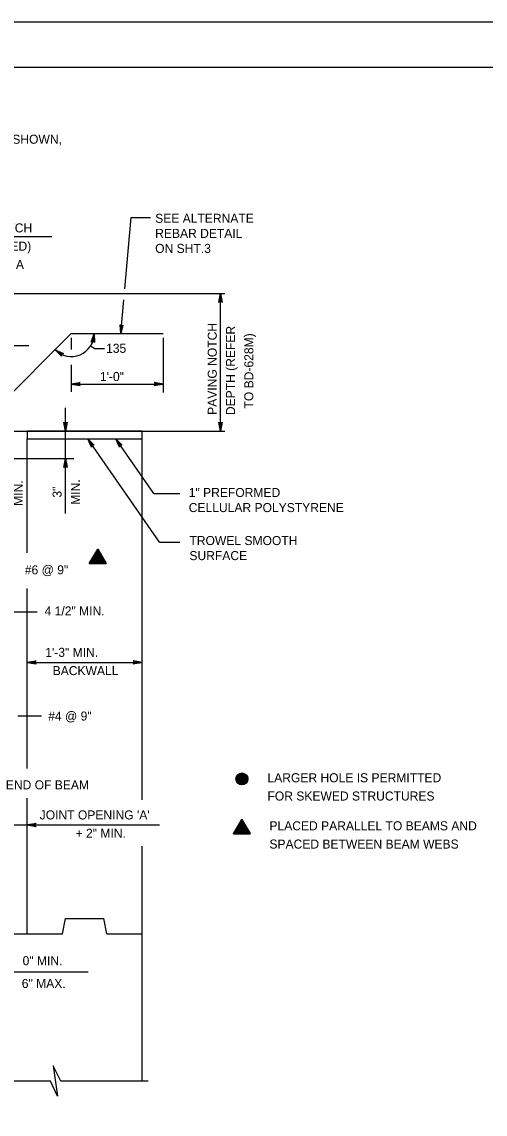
# Model space of a CAD drawing. Extents: x 640009 to 641706, y 298547 to 299735.
# Drawn here: x 641121.1 to 641275, y 299372.4 to 299735.2 of the extents above; entities that cross this region are included whole.
import ezdxf

# ---------------------------------------------------------------- set-up
doc = ezdxf.new("R2010")
doc.units = 0
doc.layers.add('1', color=7, linetype='Continuous')
doc.layers.add('PLT-BNDY', color=7, linetype='Continuous')

msp = doc.modelspace()

# ---------------------------------------------------------------- linework, layer by layer
at = {"layer": '1'}
for p, q in [((640890.47, 299720.17), (641676.47, 299720.17)), ((640890.47, 299720.17), (641676.47, 299720.17)), ((641155.32, 299646.47), (641157.48, 299670.24)), ((641157.48, 299670.24), (641163.84, 299670.24)), ((641092.08, 299663.84), (641131.12, 299663.84)), ((641088.34, 299645), (641188.58, 299645)), ((641153.97, 299631.67), (641154.99, 299642.85)), ((641187.12, 299599.28), (641187.12, 299645)), ((641074.63, 299568.75), (641137.55, 299631.67)), ((641137.55, 299631.67), (641168.03, 299631.67)), ((641137.55, 299630.26), (641137.55, 299626.36)), ((641168.03, 299630.26), (641168.03, 299612.06)), ((641099.21, 299627.64), (641123.44, 299627.64)), ((641143.97, 299627.56), (641145.38, 299626.66)), ((641145.38, 299626.66), (641148.53, 299626.66)), ((641137.55, 299621.31), (641137.55, 299612.34)), ((641137.55, 299614.87), (641168.03, 299614.87)), ((641135.6, 299590.2), (641135.6, 299607.02)), ((641110.25, 299599.28), (641188.58, 299599.28)), ((641122.94, 299599.28), (641161.04, 299599.28)), ((641122.94, 299596.74), (641161.04, 299596.74)), ((641122.94, 299558.81), (641122.94, 299596.74)), ((641166.84, 299562.38), (641143.02, 299596.74)), ((641164.96, 299578.49), (641152.31, 299596.74)), ((641161.04, 299476.82), (641161.04, 299597.38)), ((641111.67, 299590.2), (641138.43, 299590.2)), ((641135.6, 299571.86), (641135.6, 299590.2)), ((641164.96, 299578.49), (641173.62, 299578.49)), ((641166.84, 299562.38), (641173.58, 299562.38)), ((641146.32, 299556.87), (641146.32, 299556.87)), ((641122.94, 299487.19), (641122.94, 299547.03)), ((641089.62, 299539.2), (641126.24, 299539.2)), ((641122.94, 299522.45), (641161.04, 299522.45)), ((641119.82, 299504.67), (641127.64, 299504.67)), ((641122.94, 299432.28), (641122.94, 299477.38)), ((641046.74, 299468.48), (641166.85, 299468.48)), ((641194.23, 299467.14), (641194.23, 299467.14)), ((641161.04, 299432.28), (641161.04, 299461.41)), ((641134.63, 299432.28), (641135.65, 299437.38)), ((641135.65, 299437.38), (641148.34, 299437.38)), ((641149.36, 299432.28), (641148.34, 299437.38)), ((641048.65, 299432.28), (641122.94, 299432.28)), ((641122.94, 299432.28), (641134.63, 299432.28)), ((641149.36, 299432.28), (641161.04, 299432.28)), ((641161.04, 299383.32), (641161.04, 299432.28)), ((641116.39, 299419.71), (641143.2, 299419.71)), ((641130.59, 299383.32), (641081.97, 299383.32)), ((641163.08, 299383.32), (641134.11, 299383.32))]:
    msp.add_line(p, q, dxfattribs=at)
for points in [[(641187.12, 299645), (641187.68, 299642.02), (641187.52, 299642.25), (641187.32, 299642.37), (641187.12, 299642.4), (641186.92, 299642.37), (641186.72, 299642.25), (641186.56, 299642.02), (641187.12, 299645), (641186.72, 299642.25), (641186.92, 299642.37), (641187.12, 299645), (641187.12, 299642.4), (641187.32, 299642.37), (641187.12, 299645), (641187.52, 299642.25)], [(641154.56, 299634.35), (641154.35, 299634.27), (641153.97, 299631.67), (641154.56, 299634.35), (641154.69, 299634.48), (641153.97, 299631.67), (641154.08, 299634.29), (641153.89, 299634.4), (641153.97, 299631.67), (641153.78, 299634.56), (641153.89, 299634.4)], [(641145.17, 299631.67), (641145.21, 299628.63), (641145.15, 299628.76), (641145.09, 299628.89), (641145, 299628.96), (641144.91, 299629.04), (641144.82, 299629.07), (641144.72, 299629.11), (641144.62, 299629.11), (641144.52, 299629.11), (641144.41, 299629.07), (641144.3, 299629.03), (641144.2, 299628.93), (641144.11, 299628.83), (641145.17, 299631.67), (641144.2, 299628.93), (641144.3, 299629.03), (641145.17, 299631.67), (641144.41, 299629.07), (641144.52, 299629.11), (641145.17, 299631.67), (641144.62, 299629.11), (641144.72, 299629.11), (641145.17, 299631.67), (641144.82, 299629.07), (641144.91, 299629.04), (641145.17, 299631.67), (641145, 299628.96), (641145.09, 299628.89), (641145.17, 299631.67), (641145.15, 299628.76)], [(641132.17, 299626.28), (641134.94, 299625.05), (641134.8, 299625.05), (641134.66, 299625.05), (641134.55, 299625), (641134.45, 299624.95), (641134.38, 299624.88), (641134.31, 299624.8), (641134.26, 299624.71), (641134.22, 299624.62), (641134.21, 299624.5), (641134.2, 299624.39), (641134.25, 299624.26), (641134.3, 299624.13), (641132.17, 299626.28), (641134.25, 299624.26), (641134.2, 299624.39), (641132.17, 299626.28), (641134.21, 299624.5), (641134.22, 299624.62), (641132.17, 299626.28), (641134.26, 299624.71), (641134.31, 299624.8), (641132.17, 299626.28), (641134.38, 299624.88), (641134.45, 299624.95), (641132.17, 299626.28), (641134.55, 299625), (641134.66, 299625.05), (641132.17, 299626.28), (641134.8, 299625.05)], [(641137.55, 299614.87), (641140.54, 299615.43), (641140.42, 299615.35), (641140.31, 299615.27), (641140.25, 299615.17), (641140.19, 299615.07), (641140.17, 299614.97), (641140.15, 299614.87), (641140.17, 299614.77), (641140.19, 299614.67), (641140.25, 299614.57), (641140.31, 299614.47), (641140.42, 299614.39), (641140.54, 299614.32), (641137.55, 299614.87), (641140.42, 299614.39), (641140.31, 299614.47), (641137.55, 299614.87), (641140.25, 299614.57), (641140.19, 299614.67), (641137.55, 299614.87), (641140.17, 299614.77), (641140.15, 299614.87), (641137.55, 299614.87), (641140.17, 299614.97), (641140.19, 299615.07), (641137.55, 299614.87), (641140.25, 299615.17), (641140.31, 299615.27), (641137.55, 299614.87), (641140.42, 299615.35)], [(641168.03, 299614.87), (641165.05, 299614.32), (641165.17, 299614.39), (641165.28, 299614.47), (641165.34, 299614.57), (641165.4, 299614.67), (641165.42, 299614.77), (641165.43, 299614.87), (641165.42, 299614.97), (641165.4, 299615.07), (641165.34, 299615.17), (641165.28, 299615.27), (641165.17, 299615.35), (641165.05, 299615.43), (641168.03, 299614.87), (641165.17, 299615.35), (641165.28, 299615.27), (641168.03, 299614.87), (641165.34, 299615.17), (641165.4, 299615.07), (641168.03, 299614.87), (641165.42, 299614.97), (641165.43, 299614.87), (641168.03, 299614.87), (641165.42, 299614.77), (641165.4, 299614.67), (641168.03, 299614.87), (641165.34, 299614.57), (641165.28, 299614.47), (641168.03, 299614.87), (641165.17, 299614.39)], [(641135.6, 299599.28), (641135.04, 299602.26), (641135.12, 299602.15), (641135.2, 299602.03), (641135.3, 299601.97), (641135.4, 299601.91), (641135.5, 299601.9), (641135.6, 299601.88), (641135.7, 299601.9), (641135.8, 299601.91), (641135.9, 299601.97), (641136, 299602.03), (641136.08, 299602.15), (641136.16, 299602.26), (641135.6, 299599.28), (641136.08, 299602.15), (641136, 299602.03), (641135.6, 299599.28), (641135.9, 299601.97), (641135.8, 299601.91), (641135.6, 299599.28), (641135.7, 299601.9), (641135.6, 299601.88), (641135.6, 299599.28), (641135.5, 299601.9), (641135.4, 299601.91), (641135.6, 299599.28), (641135.3, 299601.97), (641135.2, 299602.03), (641135.6, 299599.28), (641135.12, 299602.15)], [(641187.12, 299599.28), (641186.56, 299602.26), (641186.72, 299602.03), (641186.92, 299601.91), (641187.12, 299601.88), (641187.32, 299601.91), (641187.52, 299602.03), (641187.68, 299602.26), (641187.12, 299599.28), (641187.52, 299602.03), (641187.32, 299601.91), (641187.12, 299599.28), (641187.12, 299601.88), (641186.92, 299601.91), (641187.12, 299599.28), (641186.72, 299602.03)], [(641143.02, 299596.74), (641145.18, 299594.61), (641145.05, 299594.66), (641144.92, 299594.71), (641144.8, 299594.7), (641144.69, 299594.69), (641144.6, 299594.65), (641144.5, 299594.6), (641144.43, 299594.53), (641144.36, 299594.46), (641144.31, 299594.36), (641144.26, 299594.25), (641144.26, 299594.11), (641144.26, 299593.97), (641143.02, 299596.74), (641144.26, 299594.11), (641144.26, 299594.25), (641143.02, 299596.74), (641144.31, 299594.36), (641144.36, 299594.46), (641143.02, 299596.74), (641144.43, 299594.53), (641144.5, 299594.6), (641143.02, 299596.74), (641144.6, 299594.65), (641144.69, 299594.69), (641143.02, 299596.74), (641144.8, 299594.7), (641144.92, 299594.71), (641143.02, 299596.74), (641145.05, 299594.66)], [(641152.31, 299596.74), (641154.46, 299594.61), (641154.33, 299594.66), (641154.2, 299594.71), (641154.09, 299594.7), (641153.97, 299594.69), (641153.88, 299594.65), (641153.79, 299594.6), (641153.71, 299594.53), (641153.64, 299594.46), (641153.59, 299594.36), (641153.55, 299594.25), (641153.55, 299594.11), (641153.55, 299593.97), (641152.31, 299596.74), (641153.55, 299594.11), (641153.55, 299594.25), (641152.31, 299596.74), (641153.59, 299594.36), (641153.64, 299594.46), (641152.31, 299596.74), (641153.71, 299594.53), (641153.79, 299594.6), (641152.31, 299596.74), (641153.88, 299594.65), (641153.97, 299594.69), (641152.31, 299596.74), (641154.09, 299594.7), (641154.2, 299594.71), (641152.31, 299596.74), (641154.33, 299594.66)], [(641135.6, 299590.2), (641136.16, 299587.22), (641136.08, 299587.33), (641136, 299587.45), (641135.9, 299587.51), (641135.8, 299587.56), (641135.7, 299587.58), (641135.6, 299587.6), (641135.5, 299587.58), (641135.4, 299587.56), (641135.3, 299587.51), (641135.2, 299587.45), (641135.12, 299587.33), (641135.04, 299587.22), (641135.6, 299590.2), (641135.12, 299587.33), (641135.2, 299587.45), (641135.6, 299590.2), (641135.3, 299587.51), (641135.4, 299587.56), (641135.6, 299590.2), (641135.5, 299587.58), (641135.6, 299587.6), (641135.6, 299590.2), (641135.7, 299587.58), (641135.8, 299587.56), (641135.6, 299590.2), (641135.9, 299587.51), (641136, 299587.45), (641135.6, 299590.2), (641136.08, 299587.33)], [(641143.54, 299555.26), (641149.11, 299555.26), (641146.32, 299560.09), (641143.54, 299555.26)], [(641143.54, 299555.26), (641146.32, 299560.09), (641149.11, 299555.26), (641143.54, 299555.26), (641146.31, 299559.95), (641149.02, 299555.33), (641143.64, 299555.31), (641146.33, 299559.8), (641148.91, 299555.39), (641143.78, 299555.38), (641146.33, 299559.66), (641148.79, 299555.48), (641143.89, 299555.44), (641146.33, 299559.52), (641148.67, 299555.54), (641144.03, 299555.53), (641146.33, 299559.35), (641148.53, 299555.61), (641144.18, 299555.61), (641146.33, 299559.17), (641148.4, 299555.69), (641144.31, 299555.69), (641146.32, 299559.01), (641148.26, 299555.78), (641144.44, 299555.77), (641146.32, 299558.85), (641148.11, 299555.87), (641144.58, 299555.84), (641146.34, 299558.69), (641147.94, 299555.94), (641144.72, 299555.93), (641146.34, 299558.53), (641147.77, 299556.05), (641144.87, 299556), (641146.34, 299558.35), (641147.63, 299556.15), (641145.01, 299556.08), (641146.33, 299558.18), (641147.48, 299556.24), (641145.18, 299556.17), (641146.34, 299558.02), (641147.34, 299556.31), (641145.35, 299556.25), (641146.33, 299557.83), (641147.18, 299556.4), (641145.52, 299556.33), (641146.33, 299557.67), (641147.01, 299556.5), (641145.65, 299556.41), (641146.33, 299557.51), (641146.85, 299556.58), (641145.81, 299556.49), (641146.33, 299557.35), (641146.72, 299556.64), (641145.94, 299556.56), (641146.33, 299557.2), (641146.6, 299556.71), (641146.07, 299556.63), (641146.33, 299557.04), (641146.49, 299556.77), (641146.21, 299556.73), (641146.33, 299556.86), (641149.1, 299555.28), (641146.33, 299556.86), (641146.33, 299560.05), (641146.33, 299556.85), (641143.54, 299555.27)], [(641122.94, 299522.45), (641125.93, 299523.01), (641125.81, 299522.93), (641125.7, 299522.85), (641125.64, 299522.75), (641125.58, 299522.65), (641125.56, 299522.55), (641125.54, 299522.45), (641125.56, 299522.35), (641125.58, 299522.25), (641125.64, 299522.15), (641125.7, 299522.05), (641125.81, 299521.97), (641125.93, 299521.89), (641122.94, 299522.45), (641125.81, 299521.97), (641125.7, 299522.05), (641122.94, 299522.45), (641125.64, 299522.15), (641125.58, 299522.25), (641122.94, 299522.45), (641125.56, 299522.35), (641125.54, 299522.45), (641122.94, 299522.45), (641125.56, 299522.55), (641125.58, 299522.65), (641122.94, 299522.45), (641125.64, 299522.75), (641125.7, 299522.85), (641122.94, 299522.45), (641125.81, 299522.93)], [(641161.04, 299522.45), (641158.06, 299521.89), (641158.18, 299521.97), (641158.29, 299522.05), (641158.35, 299522.15), (641158.41, 299522.25), (641158.43, 299522.35), (641158.44, 299522.45), (641158.43, 299522.55), (641158.41, 299522.65), (641158.35, 299522.75), (641158.29, 299522.85), (641158.18, 299522.93), (641158.06, 299523.01), (641161.04, 299522.45), (641158.18, 299522.93), (641158.29, 299522.85), (641161.04, 299522.45), (641158.35, 299522.75), (641158.41, 299522.65), (641161.04, 299522.45), (641158.43, 299522.55), (641158.44, 299522.45), (641161.04, 299522.45), (641158.43, 299522.35), (641158.41, 299522.25), (641161.04, 299522.45), (641158.35, 299522.15), (641158.29, 299522.05), (641161.04, 299522.45), (641158.18, 299521.97)], [(641192.37, 299483.2), (641192.26, 299483.82), (641192.48, 299484.55), (641193.16, 299485.32), (641193.81, 299485.6), (641194.58, 299485.6), (641195.46, 299485.2), (641195.97, 299484.61), (641196.13, 299483.97), (641196.11, 299483.24), (641195.81, 299482.61), (641195.41, 299482.18), (641194.81, 299481.91), (641194.14, 299481.78), (641193.52, 299481.94), (641192.99, 299482.26), (641192.57, 299482.76), (641192.39, 299483.2), (641192.4, 299484.33), (641192.47, 299482.97), (641192.48, 299484.6), (641192.59, 299482.61), (641192.63, 299484.82), (641192.72, 299482.52), (641192.73, 299484.95), (641192.82, 299482.39), (641192.86, 299485.1), (641192.93, 299482.26), (641192.96, 299485.22), (641193.05, 299482.2), (641193.07, 299485.27), (641193.14, 299482.12), (641193.16, 299485.38), (641193.2, 299482.07), (641193.25, 299485.41), (641193.3, 299482.03), (641193.32, 299485.46), (641193.38, 299481.99), (641193.41, 299485.51), (641193.49, 299481.88), (641193.49, 299485.54), (641193.6, 299481.87), (641193.55, 299485.56), (641193.74, 299481.84), (641193.67, 299485.6), (641193.88, 299481.8), (641193.77, 299485.61), (641193.82, 299481.82), (641193.87, 299485.66), (641193.98, 299481.79), (641193.97, 299485.65), (641194.06, 299481.77), (641194.05, 299485.67), (641194.15, 299481.76), (641194.12, 299485.67), (641194.27, 299481.79), (641194.21, 299485.67), (641194.37, 299481.77), (641194.31, 299485.7), (641194.22, 299481.76), (641194.4, 299485.67), (641194.44, 299481.78), (641194.48, 299485.69), (641194.53, 299481.79), (641194.58, 299485.65), (641194.61, 299481.8), (641194.65, 299485.63), (641194.71, 299481.83), (641194.72, 299485.61), (641194.79, 299481.85), (641194.82, 299485.6), (641194.9, 299481.91), (641194.9, 299485.58), (641194.98, 299481.93), (641194.97, 299485.54), (641195.07, 299481.95), (641195.04, 299485.49), (641195.16, 299482.01), (641195.14, 299485.47), (641195.24, 299482.06), (641195.22, 299485.42), (641195.31, 299482.08), (641195.32, 299485.36), (641195.39, 299482.15), (641195.39, 299485.31), (641195.45, 299482.21), (641195.49, 299485.23), (641195.55, 299482.3), (641195.58, 299485.12), (641195.66, 299482.4), (641195.68, 299485), (641195.79, 299482.53), (641195.76, 299484.92), (641195.92, 299482.77), (641195.87, 299484.83), (641195.87, 299482.7), (641195.94, 299484.7), (641195.97, 299482.85), (641196.02, 299484.53), (641196.03, 299482.98), (641196.09, 299484.33)], [(641196.09, 299484.33), (641196.18, 299483.64), (641195.51, 299482.61), (641194.13, 299481.98), (641192.58, 299482.91), (641192.41, 299484.26), (641193.61, 299485.3), (641194.9, 299485.3), (641195.85, 299484.65), (641196.06, 299483.56), (641195.42, 299482.34), (641195.78, 299482.78), (641193.74, 299482.01), (641192.61, 299482.74), (641192.3, 299483.81), (641192.66, 299484.61), (641193.44, 299485.28), (641194.08, 299485.57), (641195.33, 299485.22)], [(641122.94, 299468.48), (641125.93, 299469.04), (641125.81, 299468.96), (641125.7, 299468.88), (641125.64, 299468.78), (641125.58, 299468.68), (641125.56, 299468.58), (641125.54, 299468.48), (641125.56, 299468.38), (641125.58, 299468.28), (641125.64, 299468.18), (641125.7, 299468.08), (641125.81, 299468), (641125.93, 299467.92), (641122.94, 299468.48), (641125.81, 299468), (641125.7, 299468.08), (641122.94, 299468.48), (641125.64, 299468.18), (641125.58, 299468.28), (641122.94, 299468.48), (641125.56, 299468.38), (641125.54, 299468.48), (641122.94, 299468.48), (641125.56, 299468.58), (641125.58, 299468.68), (641122.94, 299468.48), (641125.64, 299468.78), (641125.7, 299468.88), (641122.94, 299468.48), (641125.81, 299468.96)], [(641191.45, 299465.53), (641197.02, 299465.53), (641194.23, 299470.36), (641191.45, 299465.53)], [(641191.45, 299465.53), (641194.23, 299470.36), (641197.02, 299465.53), (641191.45, 299465.53), (641194.23, 299470.22), (641196.93, 299465.6), (641191.55, 299465.59), (641194.24, 299470.08), (641196.82, 299465.67), (641191.69, 299465.65), (641194.24, 299469.93), (641196.7, 299465.76), (641191.8, 299465.72), (641194.24, 299469.79), (641196.58, 299465.82), (641191.94, 299465.81), (641194.24, 299469.62), (641196.44, 299465.89), (641192.09, 299465.89), (641194.24, 299469.45), (641196.31, 299465.97), (641192.22, 299465.96), (641194.23, 299469.28), (641196.17, 299466.06), (641192.36, 299466.04), (641194.23, 299469.12), (641196.02, 299466.14), (641192.49, 299466.12), (641194.25, 299468.96), (641195.85, 299466.22), (641192.63, 299466.2), (641194.25, 299468.8), (641195.68, 299466.33), (641192.78, 299466.28), (641194.25, 299468.62), (641195.54, 299466.43), (641192.92, 299466.36), (641194.24, 299468.45), (641195.39, 299466.51), (641193.09, 299466.44), (641194.25, 299468.29), (641195.25, 299466.59), (641193.26, 299466.52), (641194.24, 299468.11), (641195.09, 299466.68), (641193.43, 299466.61), (641194.24, 299467.95), (641194.92, 299466.77), (641193.56, 299466.69), (641194.24, 299467.78), (641194.76, 299466.86), (641193.72, 299466.76), (641194.24, 299467.63), (641194.63, 299466.91), (641193.85, 299466.84), (641194.24, 299467.47), (641194.51, 299466.99), (641193.98, 299466.91), (641194.24, 299467.31), (641194.4, 299467.04), (641194.13, 299467.01), (641194.24, 299467.14), (641197.01, 299465.55), (641194.24, 299467.14), (641194.24, 299470.33), (641194.24, 299467.13), (641191.45, 299465.54)], [(641134.11, 299383.32), (641131.57, 299388.5), (641132.95, 299378.35), (641130.59, 299383.32)]]:
    msp.add_lwpolyline(points, dxfattribs=at)
msp.add_lwpolyline([(641122.94, 299596.74), (641161.04, 299596.74), (641161.04, 299599.28), (641122.94, 299599.28)], close=True, dxfattribs=at)
msp.add_circle((641194.23, 299483.73), 2, dxfattribs=at)
msp.add_arc((641137.55, 299631.67), 7.62, 225, 0, dxfattribs=at)
at = {"layer": 'PLT-BNDY'}
msp.add_lwpolyline([(640850.47, 299735.17), (641691.47, 299735.17), (641691.47, 299141.17), (640850.47, 299141.17)], close=True, dxfattribs=at)

# ---------------------------------------------------------------- texts
at = {"layer": '1'}
for s, p in [('APPROACH SLAB NOT SHOWN,', (641073.36, 299694.69)), ('BEAM NOTCH', (641097.82, 299665.24)), ('SEE ALTERNATE', (641165.41, 299668.43)), ('REBAR DETAIL', (641165.41, 299663.43)), ('(AS REQUIRED)', (641093.93, 299659.17)), ('ON SHT.3', (641165.41, 299658.43)), ('SEE TABLE A', (641096.19, 299653.09)), ('135', (641149.1, 299625.25)), ('1\'-0"', (641147.06, 299615.88)), ('1" PREFORMED', (641176.56, 299577.36)), ('CELLULAR POLYSTYRENE', (641176.56, 299572.36)), ('TROWEL SMOOTH', (641176.79, 299561.41)), ('SURFACE', (641176.79, 299556.41)), ('#6 @ 9"', (641122.11, 299551.68)), ('4 1/2" MIN.', (641128.68, 299538.03)), ('1\'-3" MIN.', (641128.9, 299524.28)), ('BACKWALL', (641131.36, 299518.21)), ('#4 @ 9"', (641129.88, 299503.13)), ('END OF BEAM', (641115.8, 299480.27)), ('LARGER HOLE IS PERMITTED', (641202.71, 299482.64)), ('FOR SKEWED STRUCTURES', (641202.71, 299476.57)), ("JOINT OPENING 'A'", (641127.05, 299470.29)), ('PLACED PARALLEL TO BEAMS AND', (641203.36, 299466.68)), ('+ 2" MIN.', (641138.98, 299464.21)), ('SPACED BETWEEN BEAM WEBS', (641203.36, 299460.61)), ('0" MIN.', (641121.38, 299421.88)), ('6" MAX.', (641121.1, 299414.31))]:
    msp.add_text(s, height=3, dxfattribs=at).set_placement(p)
for s, p in [('PAVING NOTCH', (641185.87, 299604.65)), ('DEPTH (REFER', (641191.95, 299604.57)), ('TO BD-628M)', (641198.02, 299606.77)), ('MIN.', (641121.41, 299574.43)), ('MIN.', (641140.4, 299574.78)), ('3"', (641134.33, 299577.17))]:
    msp.add_text(s, height=3, rotation=90, dxfattribs=at).set_placement(p)

doc.saveas('drawing.dxf')
